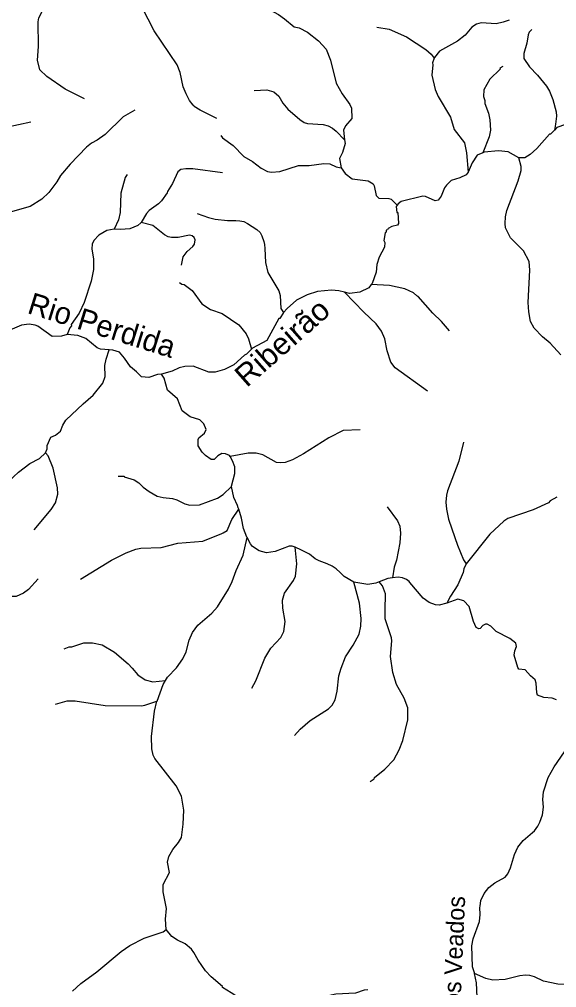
# Model space of a CAD drawing. Extents: x 280.4 to 335.6, y 8893.9 to 8949.5.
# Drawn here: x 309.18 to 314.12, y 8932.34 to 8941.25 of the extents above; entities that cross this region are included whole.
import ezdxf
from ezdxf.enums import TextEntityAlignment as Align

# ---------------------------------------------------------------- set-up
doc = ezdxf.new("R2010")
doc.units = 0
doc.header["$LTSCALE"] = 0.064
doc.layers.add('61', color=7, linetype='Continuous')
doc.layers.add('7', color=7, linetype='Continuous', lineweight=25)

msp = doc.modelspace()

# ---------------------------------------------------------------- linework, layer by layer
at = {"layer": '7'}
for points in [[(309.7774, 8940.5149), (309.599, 8940.6041), (309.4311, 8940.7223), (309.3664, 8940.7812), (309.3459, 8940.8715), (309.3537, 8940.9978), (309.3506, 8941.2233), (309.3587, 8941.2599), (309.3895, 8941.3199), (309.5582, 8941.4916), (309.6012, 8941.5505), (309.6333, 8941.6224), (309.6473, 8941.6848)], [(310.9949, 8940.3334), (310.8398, 8940.4116), (310.7843, 8940.4459), (310.783, 8940.4553), (310.7752, 8940.4582), (310.7442, 8940.5003), (310.711, 8940.5622), (310.6859, 8940.6268), (310.656, 8940.7578), (310.6307, 8940.828), (310.4189, 8941.1418), (310.3073, 8941.357), (310.2458, 8941.4287)], [(311.441, 8941.354), (311.5607, 8941.2905), (311.6173, 8941.2517), (311.704, 8941.179), (311.7505, 8941.1674), (311.8277, 8941.1272), (311.9302, 8941.0504), (311.9998, 8940.9717), (312.0397, 8940.8712), (312.0926, 8940.6588), (312.146, 8940.5612), (312.2164, 8940.4621), (312.2325, 8940.4291), (312.2369, 8940.3343), (312.1766, 8940.2668), (312.1577, 8940.2265), (312.1689, 8940.1375)], [(313.6811, 8941.2396), (313.6274, 8941.2203), (313.5613, 8941.2059), (313.4261, 8941.2153), (313.3806, 8941.2009), (313.3398, 8941.1744), (313.2778, 8941.0998), (313.2079, 8941.0459), (313.041, 8940.9539), (312.9961, 8940.8943), (312.9934, 8940.888)], [(312.4663, 8941.1732), (312.5789, 8941.1573), (312.7386, 8941.086), (312.9152, 8940.9691), (312.9664, 8940.9258), (312.9934, 8940.888)], [(313.892, 8941.153), (313.8671, 8941.1281), (313.857, 8941.103), (313.8456, 8941.0269), (313.8173, 8940.9322), (313.8158, 8940.8852), (313.8695, 8940.8101), (313.9438, 8940.7321), (314.0246, 8940.6306), (314.0526, 8940.5861), (314.0845, 8940.5093), (314.1131, 8940.3949), (314.1162, 8940.3558), (314.1069, 8940.2829), (314.0974, 8940.2274)], [(312.9934, 8940.888), (312.9757, 8940.8464), (312.9805, 8940.8292), (312.97, 8940.7341), (313.0019, 8940.6021), (313.0281, 8940.5374), (313.144, 8940.3469), (313.1764, 8940.2345), (313.2718, 8940.1115), (313.2911, 8940.02), (313.3065, 8939.8422)], [(313.6225, 8940.8138), (313.5977, 8940.7979), (313.5992, 8940.7886), (313.5055, 8940.6955), (313.4481, 8940.5996), (313.4447, 8940.5366), (313.4572, 8940.5014), (313.458, 8940.4736), (313.4929, 8940.3822), (313.5055, 8940.3221), (313.5118, 8940.2262), (313.499, 8940.1647), (313.4395, 8940.0199)], [(311.3367, 8940.5917), (311.4544, 8940.5996), (311.5197, 8940.5785), (311.5639, 8940.5388), (311.6021, 8940.4741), (311.6482, 8940.421), (311.758, 8940.3243), (311.7964, 8940.2987), (311.8288, 8940.2879), (311.972, 8940.2797), (312.0187, 8940.2666), (312.058, 8940.2457), (312.0917, 8940.2188), (312.1689, 8940.1375)], [(310.24, 8940.4109), (310.1331, 8940.3491), (309.9672, 8940.1862), (309.8926, 8940.136), (309.8404, 8940.109), (309.7947, 8940.0714), (309.644, 8939.9158), (309.558, 8939.8107), (309.5238, 8939.7525), (309.4506, 8939.6524), (309.3857, 8939.5938), (309.2763, 8939.5247), (309.0511, 8939.4614), (308.7642, 8939.3237), (308.7198, 8939.2969), (308.6132, 8939.2026), (308.5056, 8939.1249), (308.4138, 8939.0784), (308.2695, 8939.0338), (308.2315, 8939.0157), (308.187, 8938.9819), (308.1737, 8938.9478)], [(309.2829, 8940.2997), (309.0556, 8940.2506), (308.9897, 8940.2195), (308.9714, 8940.2169), (308.9251, 8940.171), (308.8637, 8940.0897), (308.8164, 8939.9888), (308.7402, 8939.7914), (308.6672, 8939.6539), (308.5989, 8939.5713), (308.5365, 8939.5106), (308.2919, 8939.3106), (308.2438, 8939.2607), (308.1952, 8939.1941), (308.1511, 8939.1028), (308.1186, 8939.0079), (308.0841, 8938.9515)], [(314.3385, 8940.2922), (314.2003, 8940.2798), (314.1203, 8940.2519), (314.0974, 8940.2274)], [(311.0294, 8940.1772), (311.0474, 8940.1578), (311.1452, 8940.0861), (311.2436, 8939.985), (311.3224, 8939.9391), (311.4004, 8939.8781), (311.4613, 8939.8477), (311.4967, 8939.8416), (311.5721, 8939.8462), (311.7456, 8939.9021), (311.8422, 8939.9024), (311.9766, 8939.9199), (312.0341, 8939.9167), (312.0908, 8939.891), (312.1364, 8939.8805)], [(314.0974, 8940.2274), (314.0636, 8940.1914), (314.0515, 8940.189), (313.9359, 8940.0577), (313.8738, 8940.002), (313.8273, 8939.9712), (313.7737, 8939.9715), (313.7713, 8939.9729)], [(312.1689, 8940.1375), (312.1729, 8940.1053), (312.1495, 8940.0217), (312.1207, 8939.9662), (312.1364, 8939.8805)], [(313.4395, 8940.0199), (313.387, 8939.9957), (313.3431, 8939.9253), (313.3065, 8939.8422)], [(313.7713, 8939.9729), (313.674, 8940.0289), (313.583, 8940.0382), (313.453, 8940.0261), (313.4395, 8940.0199)], [(314.1567, 8938.1618), (314.0584, 8938.2667), (313.9884, 8938.3254), (313.9111, 8938.4053), (313.8787, 8938.4679), (313.8636, 8938.5565), (313.8573, 8938.6405), (313.8716, 8938.9404), (313.8667, 8939.0203), (313.8149, 8939.1178), (313.6942, 8939.2371), (313.6495, 8939.3283), (313.6447, 8939.369), (313.6493, 8939.4305), (313.6621, 8939.489), (313.7648, 8939.7623), (313.7928, 8939.8547), (313.7928, 8939.8924), (313.7713, 8939.9729)], [(312.1364, 8939.8805), (312.1727, 8939.8288), (312.2385, 8939.7801), (312.3858, 8939.7615), (312.4303, 8939.7323), (312.4402, 8939.7145), (312.4583, 8939.627), (312.4851, 8939.6012), (312.5762, 8939.5999), (312.5965, 8939.5934), (312.6535, 8939.5376)], [(310.1705, 8939.8189), (310.1524, 8939.7923), (310.1104, 8939.6471), (310.1047, 8939.4697), (310.0891, 8939.4027), (310.0506, 8939.3171)], [(311.0456, 8939.8349), (310.7733, 8939.8719), (310.7086, 8939.8718), (310.6626, 8939.8641), (310.6347, 8939.8431), (310.5851, 8939.7376), (310.5397, 8939.6639), (310.5381, 8939.6518), (310.4857, 8939.5778), (310.4563, 8939.5496), (310.3717, 8939.4888), (310.3475, 8939.4594), (310.2978, 8939.3767)], [(313.3065, 8939.8422), (313.2868, 8939.817), (313.2295, 8939.7888), (313.1493, 8939.7653), (313.1046, 8939.7221), (313.0875, 8939.6969), (313.0578, 8939.6216), (313.0284, 8939.5828), (313.0006, 8939.5782), (312.9139, 8939.6185), (312.8888, 8939.6192), (312.6877, 8939.5724), (312.6619, 8939.5502), (312.6535, 8939.5376)], [(312.6535, 8939.5376), (312.6445, 8939.5239), (312.6487, 8939.4708), (312.6578, 8939.4695), (312.6653, 8939.3677), (312.6539, 8939.3523), (312.6019, 8939.3402), (312.5691, 8939.3237), (312.562, 8939.3098), (312.5524, 8939.3065), (312.5503, 8939.2901), (312.542, 8939.2816), (312.5301, 8939.2113), (312.5378, 8939.1938), (312.5362, 8939.1498), (312.4861, 8939.0595), (312.4661, 8938.9915), (312.4596, 8938.9212), (312.4214, 8938.8165), (312.4141, 8938.8065)], [(310.8138, 8939.4597), (310.9178, 8939.4226), (310.9787, 8939.4087), (311.0931, 8939.397), (311.1686, 8939.3968), (311.2068, 8939.3927), (311.2435, 8939.3856), (311.2768, 8939.3674), (311.3612, 8939.3131), (311.391, 8939.2846), (311.4071, 8939.2564), (311.426, 8939.2042), (311.4312, 8939.1744), (311.4342, 8939.1386), (311.4425, 8939.0092), (311.4624, 8938.9169), (311.5634, 8938.7483), (311.5767, 8938.7062), (311.5833, 8938.5878), (311.6076, 8938.5491)], [(310.2978, 8939.3767), (310.296, 8939.3737), (310.2683, 8939.349), (310.1942, 8939.3207), (310.1071, 8939.3139), (310.0531, 8939.3176), (310.0506, 8939.3171)], [(310.6684, 8938.9869), (310.6843, 8939.0621), (310.7217, 8939.1111), (310.7728, 8939.1561), (310.7877, 8939.1788), (310.7944, 8939.2178), (310.786, 8939.239), (310.7673, 8939.256), (310.7426, 8939.2608), (310.6388, 8939.2402), (310.5784, 8939.2401), (310.5452, 8939.2463), (310.5121, 8939.2647), (310.4048, 8939.3518), (310.2978, 8939.3767)], [(310.0506, 8939.3171), (309.983, 8939.3037), (309.9098, 8939.2605), (309.8625, 8939.2114), (309.8482, 8939.179), (309.8449, 8939.1362), (309.8591, 8939.0412), (309.8591, 8938.946), (309.8397, 8938.8397), (309.7733, 8938.6405), (309.7282, 8938.5437), (309.6549, 8938.4401), (309.657, 8938.4287), (309.6427, 8938.4089), (309.6193, 8938.3487)], [(310.6497, 8938.826), (310.6733, 8938.8105), (310.6938, 8938.8066), (310.7675, 8938.7524), (310.8576, 8938.6291), (310.9345, 8938.577), (311.0424, 8938.5412), (311.1972, 8938.4363), (311.2628, 8938.3532), (311.2855, 8938.3063), (311.3128, 8938.2123)], [(312.1688, 8938.7362), (312.1163, 8938.748), (312.0469, 8938.7556), (311.9206, 8938.7447), (311.8237, 8938.7112), (311.7277, 8938.6633), (311.6419, 8938.5873), (311.6076, 8938.5491)], [(312.4141, 8938.8065), (312.3923, 8938.7767), (312.3075, 8938.7386), (312.2128, 8938.7263), (312.1688, 8938.7362)], [(312.9311, 8937.826), (312.6345, 8938.0422), (312.5939, 8938.0921), (312.5594, 8938.1978), (312.5376, 8938.307), (312.5086, 8938.3773), (312.4595, 8938.4454), (312.3449, 8938.5536), (312.1688, 8938.7362)], [(313.1341, 8938.3807), (313.0611, 8938.4674), (312.9788, 8938.5452), (312.845, 8938.6978), (312.8317, 8938.7021), (312.8032, 8938.7301), (312.7234, 8938.7678), (312.5803, 8938.7973), (312.4141, 8938.8065)], [(311.6076, 8938.5491), (311.5721, 8938.4955), (311.5638, 8938.4941), (311.455, 8938.2937), (311.3214, 8938.221), (311.3128, 8938.2123)], [(309.6193, 8938.3487), (309.5668, 8938.3316), (309.4813, 8938.3301), (309.3483, 8938.4233), (309.3242, 8938.4342), (309.2674, 8938.4421), (309.1971, 8938.4326), (309.0914, 8938.3879), (309.0383, 8938.3738), (309.0101, 8938.3804)], [(310.0043, 8938.2067), (309.9231, 8938.2137), (309.8936, 8938.2248), (309.7903, 8938.3109), (309.7159, 8938.3396), (309.6193, 8938.3487)], [(309.42, 8937.2601), (309.4347, 8937.2968), (309.4344, 8937.3257), (309.4682, 8937.4046), (309.5105, 8937.4224), (309.5573, 8937.4591), (309.5767, 8937.5145), (309.6049, 8937.5594), (309.7647, 8937.7113), (309.8559, 8937.7882), (309.947, 8937.899), (309.9678, 8937.9616), (309.965, 8938.0639), (309.9764, 8938.1222), (310.0043, 8938.2067)], [(310.4849, 8937.9814), (310.4488, 8937.9791), (310.3685, 8937.9513), (310.3028, 8937.9576), (310.2557, 8938.0055), (310.1998, 8938.0505), (310.1464, 8938.131), (310.0989, 8938.1862), (310.0389, 8938.2037), (310.0043, 8938.2067)], [(311.3128, 8938.2123), (311.2681, 8938.1668), (311.249, 8938.1574)], [(311.249, 8938.1574), (311.1494, 8938.0674), (311.0644, 8938.0244), (310.9797, 8938.0015), (310.9206, 8938.0007), (310.7775, 8938.055), (310.7003, 8938.0536), (310.647, 8938.0407), (310.5836, 8938.0099), (310.4849, 8937.9814)], [(310.675, 8937.6461), (310.6328, 8937.755), (310.5406, 8937.8347), (310.5102, 8937.9473), (310.4849, 8937.9814)], [(311.1164, 8937.2245), (311.1111, 8937.2336), (311.0736, 8937.2515), (311.0393, 8937.2537), (311.002, 8937.2306), (310.9702, 8937.1975), (310.943, 8937.1979), (310.8899, 8937.236), (310.8598, 8937.2658), (310.8217, 8937.3224), (310.8219, 8937.3805), (310.8295, 8937.3957), (310.8802, 8937.4409), (310.8967, 8937.4746), (310.8747, 8937.5253), (310.8383, 8937.5637), (310.7477, 8937.5919), (310.675, 8937.6461)], [(312.3106, 8937.4716), (312.1551, 8937.4634), (312.0241, 8937.3986), (311.7905, 8937.2489), (311.6896, 8937.1946), (311.6209, 8937.1707), (311.5824, 8937.1661), (311.5434, 8937.1714), (311.4162, 8937.2397), (311.3569, 8937.2573), (311.2824, 8937.2571), (311.1164, 8937.2245)], [(313.2637, 8937.3577), (313.2202, 8937.1823), (313.1157, 8936.9092), (313.1056, 8936.8694), (313.1009, 8936.8045), (313.1059, 8936.7406), (313.1244, 8936.6478), (313.1556, 8936.5588), (313.2073, 8936.4111), (313.2637, 8936.2759), (313.286, 8936.2378)], [(308.5313, 8936.4494), (308.5734, 8936.5663), (308.627, 8936.677), (308.6501, 8936.7102), (308.7077, 8936.7678), (308.7925, 8936.8317), (308.9821, 8936.9226), (309.0313, 8936.9522), (309.1694, 8937.0821), (309.2759, 8937.1597), (309.3649, 8937.2077), (309.42, 8937.2601)], [(309.3153, 8936.5507), (309.4716, 8936.7374), (309.5094, 8936.798), (309.5326, 8936.8783), (309.5278, 8936.938), (309.4881, 8937.119), (309.4432, 8937.2325), (309.42, 8937.2601)], [(311.1301, 8936.9502), (311.1294, 8936.954), (311.1606, 8937.0701), (311.1589, 8937.1308), (311.1385, 8937.1868), (311.1164, 8937.2245)], [(310.0883, 8937.0461), (310.1409, 8937.0443), (310.1432, 8937.0381), (310.2333, 8937.0108), (310.2781, 8936.9837), (310.3171, 8936.9435), (310.3713, 8936.903), (310.4462, 8936.8611), (310.4999, 8936.8482), (310.5856, 8936.8403), (310.6273, 8936.8282), (310.6988, 8936.7887), (310.7444, 8936.7788), (310.8338, 8936.7813), (311.0009, 8936.843), (311.0516, 8936.8758), (311.1301, 8936.9502)], [(311.1951, 8936.7413), (311.1913, 8936.7542), (311.1851, 8936.775), (311.1492, 8936.8499), (311.1301, 8936.9502)], [(314.1208, 8936.8518), (314.0579, 8936.8183), (314.0433, 8936.8004), (313.9013, 8936.734), (313.6711, 8936.6538), (313.6327, 8936.6313), (313.5044, 8936.5109), (313.286, 8936.2378)], [(312.5618, 8936.7625), (312.6553, 8936.6336), (312.6769, 8936.5837), (312.6834, 8936.5216), (312.6769, 8936.4312), (312.6452, 8936.2728), (312.6255, 8936.2064), (312.6093, 8936.1085)], [(309.7401, 8936.0976), (310.0248, 8936.2717), (310.1597, 8936.3392), (310.2493, 8936.3727), (310.2941, 8936.3823), (310.482, 8936.3871), (310.6363, 8936.4271), (310.8658, 8936.4463), (311.04, 8936.5168), (311.0537, 8936.5224), (311.0879, 8936.5452), (311.131, 8936.6455), (311.1951, 8936.7413)], [(311.2715, 8936.4804), (311.2695, 8936.4841), (311.2378, 8936.564), (311.2209, 8936.6582), (311.1951, 8936.7413)], [(310.5214, 8935.1637), (310.5416, 8935.1969), (310.6219, 8935.2821), (310.6827, 8935.3632), (310.7128, 8935.4301), (310.7388, 8935.5363), (310.7712, 8935.6074), (310.8203, 8935.6755), (310.9472, 8935.7848), (311.0004, 8935.8413), (311.1021, 8936.004), (311.1356, 8936.0744), (311.1716, 8936.1776), (311.2369, 8936.3184), (311.2715, 8936.4804)], [(311.7134, 8936.3915), (311.6878, 8936.4), (311.6598, 8936.4012), (311.5307, 8936.3525), (311.4495, 8936.3394), (311.3822, 8936.358), (311.3235, 8936.3977), (311.3038, 8936.4211), (311.2715, 8936.4804)], [(311.3169, 8935.0931), (311.353, 8935.1615), (311.4344, 8935.37), (311.4893, 8935.4617), (311.5819, 8935.5609), (311.6094, 8935.6152), (311.6215, 8935.7091), (311.5994, 8935.8319), (311.5992, 8935.9035), (311.6156, 8935.9684), (311.6982, 8936.085), (311.7178, 8936.1256), (311.7286, 8936.2393), (311.7134, 8936.3915)], [(312.2536, 8936.0707), (312.1642, 8936.1215), (312.1288, 8936.1578), (312.091, 8936.1916), (312.0549, 8936.2159), (312.0075, 8936.2396), (311.9343, 8936.2644), (311.8997, 8936.2839), (311.847, 8936.328), (311.7728, 8936.3639), (311.7134, 8936.3915)], [(313.286, 8936.2378), (313.2642, 8936.1917), (313.2595, 8936.1585), (313.2087, 8936.0465), (313.1413, 8935.94), (313.1094, 8935.8763)], [(309.3501, 8936.1011), (309.2612, 8936.0023), (309.2162, 8935.9682), (309.1498, 8935.9375), (309.0843, 8935.9378), (308.9962, 8935.9521), (308.7947, 8936.0414), (308.7492, 8936.0497), (308.6813, 8936.0497), (308.5029, 8936.0289), (308.3693, 8936.0019), (308.2119, 8935.9569), (307.9895, 8935.8662), (307.8927, 8935.8533), (307.7545, 8935.854)], [(311.7088, 8934.6587), (311.7611, 8934.7164), (311.8519, 8934.7958), (312.0197, 8934.9047), (312.0542, 8934.9378), (312.0815, 8934.9881), (312.101, 8935.0655), (312.1173, 8935.2069), (312.137, 8935.2789), (312.1784, 8935.3835), (312.2488, 8935.4891), (312.3013, 8935.5911), (312.3186, 8935.6636), (312.3218, 8935.7363), (312.3059, 8935.8754), (312.2536, 8936.0707)], [(312.4877, 8936.0719), (312.4561, 8936.0601), (312.3827, 8936.0467), (312.2536, 8936.0707)], [(312.4033, 8934.2357), (312.4395, 8934.2598), (312.4428, 8934.272), (312.5383, 8934.3486), (312.6213, 8934.4367), (312.6692, 8934.5263), (312.7044, 8934.6143), (312.7505, 8934.8046), (312.749, 8934.9142), (312.7161, 8935.0037), (312.6448, 8935.1276), (312.6136, 8935.2394), (312.5923, 8935.3853), (312.6034, 8935.5292), (312.6003, 8935.558), (312.541, 8935.733), (312.5426, 8935.8124), (312.5457, 8935.9617), (312.5159, 8936.0374), (312.4877, 8936.0719)], [(312.6093, 8936.1085), (312.5676, 8936.1019), (312.4877, 8936.0719)], [(313.1094, 8935.8763), (313.0381, 8935.859), (313.004, 8935.8599), (312.945, 8935.8838), (312.8904, 8935.9214), (312.7694, 8936.0679), (312.7633, 8936.0752), (312.7389, 8936.0955), (312.701, 8936.1102), (312.6617, 8936.1168), (312.6093, 8936.1085)], [(314.1186, 8934.9867), (314.0779, 8935.0037), (314.0005, 8935.0089), (313.9439, 8935.0297), (313.9354, 8935.0505), (313.9305, 8935.1392), (313.9219, 8935.1718), (313.8797, 8935.207), (313.8282, 8935.2642), (313.7718, 8935.2694), (313.7627, 8935.2844), (313.7295, 8935.3996), (313.7327, 8935.4372), (313.7485, 8935.4766), (313.7438, 8935.5097), (313.6875, 8935.5524), (313.5625, 8935.6146), (313.5128, 8935.6664), (313.4812, 8935.6845), (313.4632, 8935.6831), (313.4412, 8935.6715), (313.4148, 8935.6422), (313.4024, 8935.6393), (313.3782, 8935.6528), (313.3554, 8935.7084), (313.3137, 8935.8459), (313.2649, 8935.8989), (313.2103, 8935.9118), (313.1094, 8935.8763)], [(309.5913, 8935.4557), (309.6363, 8935.4756), (309.6615, 8935.4759), (309.7702, 8935.5121), (309.852, 8935.5104), (309.9383, 8935.4917), (310.0526, 8935.426), (310.1783, 8935.3178), (310.2146, 8935.2778), (310.2681, 8935.2187), (310.3351, 8935.1721), (310.406, 8935.1526), (310.5214, 8935.1637)], [(310.4438, 8934.9738), (310.4439, 8934.974), (310.4991, 8935.1271), (310.5214, 8935.1637)], [(309.5098, 8934.9462), (309.6167, 8934.9767), (309.6918, 8934.9783), (309.9671, 8934.9367), (310.3005, 8934.9319), (310.3332, 8934.9369), (310.4438, 8934.9738)], [(310.5284, 8932.8758), (310.5229, 8932.9711), (310.5308, 8933.0671), (310.5011, 8933.2224), (310.5005, 8933.2902), (310.5594, 8933.399), (310.5406, 8933.4929), (310.5531, 8933.5462), (310.5896, 8933.6102), (310.6415, 8933.6739), (310.6681, 8933.7221), (310.6842, 8933.8427), (310.6907, 8933.9723), (310.6696, 8934.1009), (310.6207, 8934.1956), (310.4225, 8934.4482), (310.4088, 8934.4792), (310.3965, 8934.5352), (310.3933, 8934.651), (310.4194, 8934.8834), (310.4438, 8934.9738)], [(313.9145, 8933.7838), (313.9461, 8933.8255), (313.9647, 8933.8611), (313.9884, 8933.9307), (313.9979, 8934.0003), (313.9918, 8934.0714), (313.9983, 8934.1425), (314.0409, 8934.2716), (314.0962, 8934.3707), (314.1908, 8934.5079), (314.2227, 8934.5689), (314.2479, 8934.635), (314.2716, 8934.6662), (314.31, 8934.6935)], [(313.3641, 8932.4699), (313.3631, 8932.4752), (313.3444, 8932.5318), (313.3393, 8932.7256), (313.352, 8932.7888), (313.4095, 8932.9495), (313.4158, 8933.0127), (313.4128, 8933.0784), (313.414, 8933.0882), (313.4207, 8933.1405), (313.4511, 8933.2073), (313.4943, 8933.2622), (313.5502, 8933.3038), (313.6456, 8933.3565), (313.6694, 8933.3868), (313.6943, 8933.4421), (313.7309, 8933.5647), (313.7629, 8933.6306), (313.8109, 8933.694), (313.8967, 8933.7671), (313.9145, 8933.7838)], [(309.6654, 8932.3087), (309.7423, 8932.3767), (309.8919, 8932.4852), (310.1151, 8932.6737), (310.1956, 8932.7283), (310.3268, 8932.7955), (310.5005, 8932.8523), (310.5284, 8932.8758)], [(312.3824, 8932.3183), (312.3494, 8932.3164), (312.2685, 8932.2899), (312.0886, 8932.2794), (312.0181, 8932.2658), (311.8598, 8932.2168), (311.7295, 8932.1872), (311.5696, 8932.1299), (311.5047, 8932.1237), (311.4431, 8932.1268), (311.38, 8932.1392), (311.2799, 8932.1919), (311.1267, 8932.2908), (311.0467, 8932.3425), (311.0465, 8932.3493), (310.9413, 8932.4408), (310.8886, 8932.4952), (310.8223, 8932.5915), (310.7838, 8932.6635), (310.7598, 8932.6926), (310.7017, 8932.7431), (310.6317, 8932.7752), (310.5796, 8932.8108), (310.5284, 8932.8758)], [(313.3236, 8931.3579), (313.3233, 8931.3727), (313.2995, 8931.5256), (313.3009, 8931.7757), (313.3646, 8932.0876), (313.387, 8932.2523), (313.3805, 8932.3833), (313.3641, 8932.4699)], [(315.182, 8932.2188), (314.9256, 8932.3041), (314.8737, 8932.3151), (314.539, 8932.3247), (314.289, 8932.3666), (314.1286, 8932.3719), (313.9981, 8932.4003), (313.914, 8932.4383), (313.8707, 8932.4512), (313.8327, 8932.4541), (313.7805, 8932.4482), (313.6447, 8932.4144), (313.5328, 8932.4084), (313.4664, 8932.4229), (313.3641, 8932.4699)]]:
    msp.add_lwpolyline(points, dxfattribs=at)

# ---------------------------------------------------------------- texts
at = {"layer": '61'}
for s, height, rotation, p in [('Rio Perdida', 0.2, 342.646, (309.9084, 8938.3384)), ('Córrego Brejo dos Veados', 0.16, 87.518, (313.2234, 8931.9195))]:
    msp.add_text(s, height=height, rotation=rotation, dxfattribs=at).set_placement(p, align=Align.CENTER)
at = {"layer": '61', "width": 1.05}
msp.add_text('Ribeirão', height=0.2, rotation=41.424, dxfattribs=at).set_placement((311.6605, 8938.1996), align=Align.CENTER)

doc.saveas('drawing.dxf')
